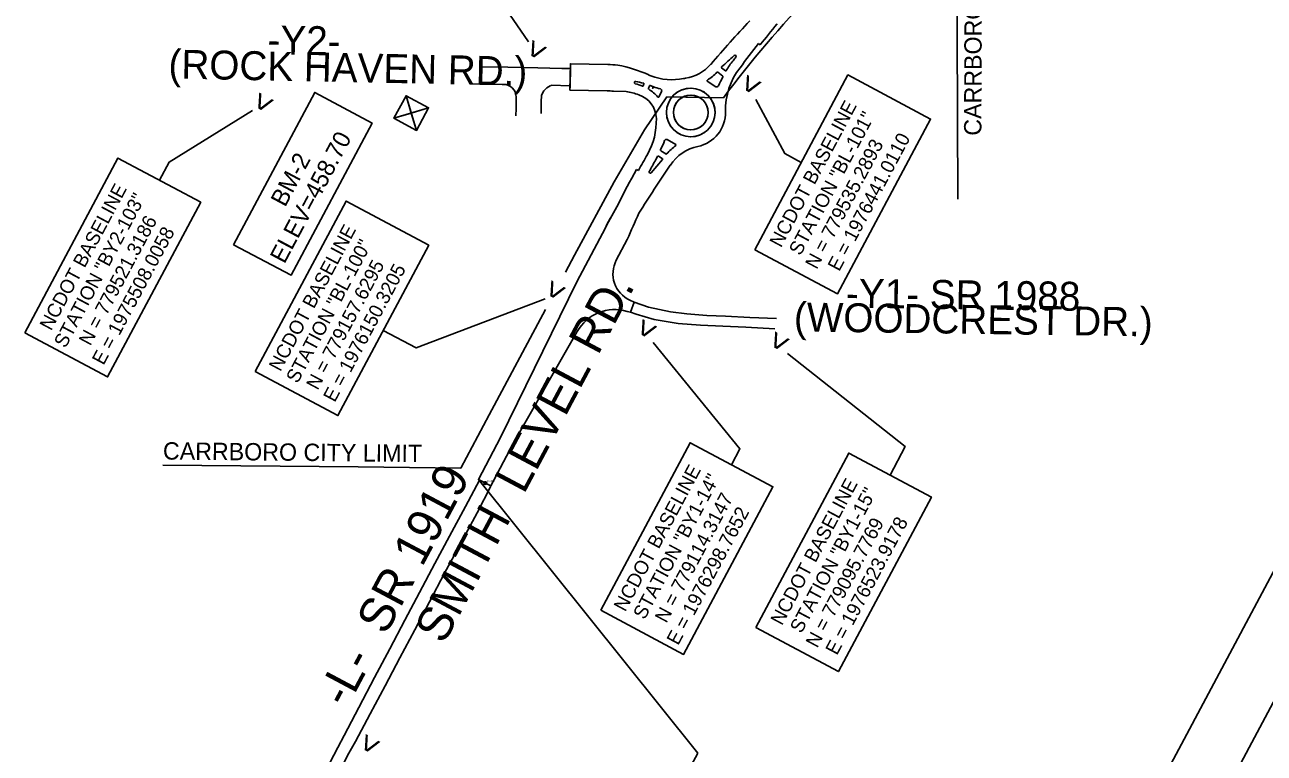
# Model space of a CAD drawing. Extents: x 1970823 to 1988115, y 770601 to 786368.
# Drawn here: x 1975224 to 1977367, y 778367 to 779627 of the extents above; entities that cross this region are included whole.
import ezdxf

# ---------------------------------------------------------------- set-up
doc = ezdxf.new("R2010")
doc.units = 0
for name, color, linetype in [('Cogo Default Point CELL', 7, 'Continuous'), ('COGO Default Point Number', 7, 'Continuous'), ('CTL Sheet Border CELL', 7, 'Continuous'), ('CTL Sheet Text', 7, 'Continuous'), ('CTL Supplemental Horizontal and Vertical Text', 7, 'Continuous'), ('Default', 7, 'Continuous'), ('Old_Level_12', 7, 'Continuous'), ('Old_Level_3', 7, 'Continuous'), ('Old_Level_32', 7, 'Continuous'), ('Old_Level_57', 7, 'Continuous')]:
    doc.layers.add(name, color=color, linetype=linetype)

msp = doc.modelspace()

# ---------------------------------------------------------------- linework, layer by layer
at = {"layer": 'Cogo Default Point CELL'}
for points in [[(1976020.6, 778837.3), (1976020.6, 778834.3)], [(1976017.6, 778834.3), (1976020.6, 778834.3)], [(1976020.6, 778834.3), (1976023.6, 778834.3)], [(1976020.6, 778834.3), (1976020.6, 778831.3)]]:
    msp.add_lwpolyline(points, dxfattribs=at)
msp.add_circle((1976020.6, 778834.3), 2.34, dxfattribs=at)
at = {"layer": 'CTL Sheet Border CELL'}
msp.add_lwpolyline([(1977121.9, 778191.4), (1979828.5, 783270.4), (1979922.1, 783220.5), (1977215.6, 778141.6)], close=True, dxfattribs=at)
at = {"layer": 'CTL Sheet Text'}
for q in [(1976008.8, 778840.5), (1975683.2, 777045.4)]:
    msp.add_line((1976387.7, 778367.4), q, dxfattribs=at)
at = {"layer": 'CTL Supplemental Horizontal and Vertical Text'}
for points in [[(1975932.9, 779797.4), (1975972.3, 779776.4), (1976095.3, 779597.5)], [(1975457.1, 779358.1), (1975473.8, 779389.4), (1975618.1, 779478.3)], [(1976566.9, 779388.8), (1976538.2, 779404), (1976488.3, 779497.8)], [(1975844.3, 779098.3), (1975901.2, 779067.9), (1976123.8, 779152.8)], [(1976446.2, 778865.8), (1976460.7, 778893.2), (1976310.6, 779077.3)], [(1976720.4, 778848.1), (1976746.5, 778897.3), (1976542.8, 779058.3)]]:
    msp.add_lwpolyline(points, dxfattribs=at)
at = {"layer": 'Default'}
for p, q in [((1976492.7, 779594.4), (1976495.8, 779591.9)), ((1976167.8, 779559.3), (1976166.8, 779513.8)), ((1976167.8, 779559.3), (1976232.3, 779558)), ((1976293.7, 779521.2), (1976294.9, 779524.5)), ((1976304.5, 779521.3), (1976302.5, 779516.6)), ((1976404.4, 779529.4), (1976419.2, 779519.7)), ((1976166.8, 779513.8), (1976231.4, 779512.5)), ((1976242.1, 779512.1), (1976263.9, 779511.6)), ((1976320.4, 779501.8), (1976325.2, 779511.5)), ((1976334.9, 779428.2), (1976349.8, 779419.5)), ((1976307.2, 779370.9), (1976326.7, 779394)), ((1976319.9, 779399.7), (1976326.4, 779395.5)), ((1976281.8, 779376.5), (1976285.3, 779374.5)), ((1976178.7, 779182.3), (1976228.2, 779275.9)), ((1976247, 779219.5), (1976266, 779255.5)), ((1976047.1, 778913), (1976178.7, 779182.3)), ((1976278.1, 779147.2), (1976270.5, 779150.7)), ((1976278.1, 779147.2), (1976271.6, 779129.6)), ((1976271.6, 779129.6), (1976266, 779131.2)), ((1976068.3, 778901.8), (1976179.3, 779096.5)), ((1976008.8, 778840.5), (1976047.1, 778913)), ((1976030, 778829.3), (1976068.3, 778901.8)), ((1976008.8, 778840.5), (1976030, 778829.3))]:
    msp.add_line(p, q, dxfattribs=at)
for points in [[(1976492.7, 779594.4), (1976495.8, 779591.9)], [(1976232.3, 779558), (1976167.8, 779559.3), (1976167.6, 779550.9), (1976167, 779520.9), (1976166.8, 779513.8), (1976231.4, 779512.5)], [(1976431.1, 779537.9), (1976422.3, 779544.7)], [(1976422.3, 779544.7), (1976431.1, 779537.9)], [(1976429, 779552.2), (1976435.6, 779547.1)], [(1976435.6, 779547.1), (1976429, 779552.2)], [(1976293.7, 779521.2), (1976294.9, 779524.5)], [(1976294.9, 779524.5), (1976293.7, 779521.2)], [(1976304.5, 779521.3), (1976302.5, 779516.6)], [(1976302.5, 779516.6), (1976304.5, 779521.3)], [(1976404.4, 779529.4), (1976419.2, 779519.7)], [(1976419.2, 779519.7), (1976404.4, 779529.4)], [(1976242.1, 779512.1), (1976263.9, 779511.6)], [(1976311.1, 779519.6), (1976309.8, 779516.7), (1976311.1, 779519.6)], [(1976320.4, 779501.8), (1976325.2, 779511.5)], [(1976325.2, 779511.5), (1976320.4, 779501.8)], [(1976349.8, 779419.5), (1976334.9, 779428.2)], [(1976334.9, 779428.2), (1976349.8, 779419.5)], [(1976307.2, 779370.9), (1976326.7, 779394)], [(1976326.7, 779394), (1976307.2, 779370.9)], [(1976326.4, 779395.5), (1976319.9, 779399.7)], [(1976319.9, 779399.7), (1976326.4, 779395.5)], [(1976323.9, 779409), (1976332.8, 779403.3)], [(1976332.8, 779403.3), (1976323.9, 779409)], [(1976285.3, 779374.5), (1976281.8, 779376.5)], [(1976250.7, 779317.3), (1976250.6, 779317.2)], [(1976228.2, 779275.9), (1976178.7, 779182.3), (1976047.1, 778913), (1976008.8, 778840.5), (1976010.8, 778839.5), (1976030, 778829.3), (1976068.3, 778901.8), (1976179.4, 779096.2)], [(1976247, 779219.5), (1976266, 779255.5)], [(1976266, 779131.2), (1976271.6, 779129.6), (1976278.1, 779147.2), (1976270.5, 779150.7)]]:
    msp.add_lwpolyline(points, dxfattribs=at)
for points in [[(1976486.3, 779237.6), (1976647.4, 779539.9), (1976790.4, 779463.7), (1976629.3, 779161.4)], [(1975585.4, 779246.4), (1975725.7, 779509.7), (1975824.9, 779456.8), (1975684.7, 779193.5)], [(1975224.5, 779093.9), (1975385.6, 779396.2), (1975528.6, 779320), (1975367.5, 779017.7)], [(1975622.8, 779027.1), (1975779.8, 779321.8), (1975922.8, 779245.6), (1975765.7, 778950.9)], [(1976220.3, 778614.3), (1976374.7, 778903.9), (1976517.7, 778827.8), (1976363.3, 778538.1)], [(1976488.1, 778584.6), (1976648.9, 778886.2), (1976791.8, 778810), (1976631.1, 778508.4)]]:
    msp.add_lwpolyline(points, close=True, dxfattribs=at)
for radius in [42, 30]:
    msp.add_circle((1976375.8, 779475.1), radius, dxfattribs=at)
for centre, radius, start, end in [((1977876.3, 778316.7), 1921, 136.7176, 139.7332), ((1977876.3, 778316.7), 1921, 136.7176, 139.7332), ((1977976, 778436), 1878, 140.5977, 142.0125), ((1977976, 778436), 1878, 140.6002, 142.0125), ((1977976.4, 778436.4), 1882, 142.0289, 143.6297), ((1977976.4, 778436.4), 1882, 142.0289, 143.6297), ((1977729.6, 778130.3), 1928.2, 131.5446, 132.4191), ((1977729.6, 778130.3), 1928.2, 131.5446, 132.4191), ((1977729.6, 778130.3), 1928.2, 131.5446, 132.4191), ((1976555.7, 779478.9), 137, 141.2395, 150.018), ((1976555.7, 779478.9), 137, 141.2395, 150.018), ((1976555.7, 779478.9), 137, 141.2395, 150.018), ((1977926.9, 778377.9), 1895.5, 141.0068, 141.2395), ((1977926.9, 778377.9), 1895.5, 141.0068, 141.2395), ((1977926.9, 778377.9), 1895.5, 141.0068, 141.2395), ((1976452.2, 779571.9), 2, 321.0068, 131.5446), ((1976452.2, 779571.9), 2, 321.0068, 131.5446), ((1976452.2, 779571.9), 2, 321.0068, 131.5446), ((1976227.7, 779333.2), 224.8, 84.44, 88.8319), ((1976227.7, 779333.2), 224.8, 84.44, 88.8319), ((1976208.6, 779335), 225.7, 65.2309, 79.5481), ((1976208.6, 779335), 225.7, 65.2309, 79.5481), ((1976354.8, 779608.5), 75, 278.9494, 318.0674), ((1976354.8, 779608.5), 75, 278.9494, 318.0674), ((1976354.8, 779608.5), 92, 302.6674, 316.0364), ((1976354.8, 779608.5), 92, 302.6674, 316.0364), ((1976354.8, 779608.5), 92, 302.6674, 316.0364), ((1976421.7, 779543.9), 1, 52.2081, 136.0364), ((1976421.7, 779543.9), 1, 52.2081, 136.0364), ((1976421.7, 779543.9), 1, 52.2081, 136.0364), ((1976429.6, 779553), 1, 132.4191, 231.9065), ((1976429.6, 779553), 1, 132.4191, 231.9065), ((1976429.6, 779553), 1, 132.4191, 231.9065), ((1976436.2, 779547.8), 1, 231.9065, 330.018), ((1976436.2, 779547.8), 1, 231.9065, 330.018), ((1976436.2, 779547.8), 1, 231.9065, 330.018), ((1976555.7, 779478.9), 120, 142.1787, 181.1936), ((1976555.7, 779478.9), 120, 142.1787, 181.1936), ((1976280.2, 779526.8), 2, 79.4395, 253.1009), ((1976280.2, 779526.8), 2, 79.4395, 253.1009), ((1976280.2, 779526.8), 2, 79.4395, 253.1009), ((1976221.4, 779333.1), 200.4, 69.2746, 73.1009), ((1976221.4, 779333.1), 200.4, 69.2746, 73.1009), ((1976221.4, 779333.1), 200.4, 69.2746, 73.1009), ((1976243.4, 779329.6), 202.6, 75.4924, 79.4395), ((1976243.4, 779329.6), 202.6, 75.4924, 79.4395), ((1976243.4, 779329.6), 202.6, 75.4924, 79.4395), ((1976292.8, 779521.5), 1, 241.0006, 340.6492), ((1976292.8, 779521.5), 1, 241.0006, 340.6492), ((1976292.8, 779521.5), 1, 241.0006, 340.6492), ((1976293.9, 779524.8), 1, 340.6492, 75.4924), ((1976293.9, 779524.8), 1, 340.6492, 75.4924), ((1976293.9, 779524.8), 1, 340.6492, 75.4924), ((1976227.7, 779333.2), 220, 68.8787, 69.9595), ((1976227.7, 779333.2), 220, 68.8787, 69.9595), ((1976305.4, 779520.9), 1, 66.3367, 157.7992), ((1976305.4, 779520.9), 1, 66.3367, 157.7992), ((1976305.4, 779520.9), 1, 66.3367, 157.7992), ((1976352.7, 779628.9), 116.9, 246.3367, 255.4103), ((1976352.7, 779628.9), 116.9, 246.3367, 249.1392), ((1976352.7, 779628.9), 116.9, 246.3367, 249.1392), ((1976343, 779631.8), 100, 248.8787, 281.7975), ((1976343, 779631.8), 100, 248.8787, 281.7975), ((1976375.8, 779475.1), 60, 98.9494, 101.7975), ((1976375.8, 779475.1), 60, 98.9494, 101.7975), ((1976405, 779530.2), 1, 122.6674, 236.722), ((1976405, 779530.2), 1, 122.6674, 236.722), ((1976405, 779530.2), 1, 122.6674, 236.722), ((1976420.8, 779522.2), 3, 236.722, 337.1435), ((1976420.8, 779522.2), 3, 236.722, 337.1435), ((1976420.8, 779522.2), 3, 236.722, 337.1435), ((1976548.8, 779468.2), 135.8, 149.792, 157.1435), ((1976548.8, 779468.2), 135.8, 149.792, 157.1435), ((1976548.8, 779468.2), 135.8, 149.792, 157.1435), ((1976430.5, 779537.1), 1, 329.792, 52.2081), ((1976430.5, 779537.1), 1, 329.792, 52.2081), ((1976430.5, 779537.1), 1, 329.792, 52.2081), ((1976227.7, 779331.4), 181.1, 87.2818, 88.8319), ((1976227.7, 779331.4), 181.1, 87.2818, 88.8319), ((1976231.4, 779329), 183.3, 86.6752, 88.4912), ((1976231.4, 779329), 183.3, 86.6752, 88.4912), ((1976227.7, 779333.2), 182, 71.3914, 78.5258), ((1976227.7, 779333.2), 182, 71.3914, 78.5258), ((1976271.4, 779463.2), 44.9, 1.7826, 71.2258), ((1976271.4, 779463.2), 44.9, 1.7826, 71.2258), ((1976303.5, 779516.2), 1, 157.7992, 238.9047), ((1976303.5, 779516.2), 1, 157.7992, 238.9047), ((1976303.5, 779516.2), 1, 157.7992, 238.9047), ((1976271.5, 779463.1), 61, 39.1963, 58.9047), ((1976271.5, 779463.1), 61, 39.1963, 58.9047), ((1976271.5, 779463.1), 61, 39.1963, 58.9047), ((1976352.7, 779628.9), 116.9, 249.1392, 255.4103), ((1976352.7, 779628.9), 116.9, 249.1392, 255.4103), ((1976319.5, 779502.3), 1, 219.1963, 333.6015), ((1976319.5, 779502.3), 1, 219.1963, 333.6015), ((1976319.5, 779502.3), 1, 219.1963, 333.6015), ((1976322.5, 779512.8), 3, 333.6015, 75.4103), ((1976322.5, 779512.8), 3, 333.6015, 75.4103), ((1976322.5, 779512.8), 3, 333.6015, 75.4103), ((1976375.8, 779475.1), 42, 55.3305, 235.3305), ((1976375.8, 779475.1), 42, 55.3305, 235.3305), ((1976375.8, 779475.1), 30, 55.1797, 235.1797), ((1976375.8, 779475.1), 42, 235.3305, 55.3305), ((1976375.8, 779475.1), 42, 235.3305, 55.3305), ((1976375.8, 779475.1), 30, 235.1797, 55.1797), ((1976196.2, 779461.3), 120.1, 330.7248, 1.5795), ((1976196.2, 779461.3), 120.1, 330.7248, 1.5795), ((1976375.8, 779475.1), 60, 281.7976, 1.1936), ((1976375.8, 779475.1), 60, 281.7976, 1.1936), ((1976202, 779472.3), 136.4, 332.9755, 340.4471), ((1976202, 779472.3), 136.4, 332.9755, 340.4471), ((1976202, 779472.3), 136.4, 332.9755, 340.4471), ((1976333.4, 779425.6), 3, 59.8207, 160.4471), ((1976333.4, 779425.6), 3, 59.8207, 160.4471), ((1976333.4, 779425.6), 3, 59.8207, 160.4471), ((1976403.4, 779343), 92, 125.5201, 138.8781), ((1976403.4, 779343), 92, 125.5201, 138.8781), ((1976403.4, 779343), 92, 125.5201, 138.8781), ((1976403.4, 779343), 75, 101.7976, 147.0005), ((1976403.4, 779343), 75, 101.7976, 147.0005), ((1976349.3, 779418.7), 1, 305.5201, 59.8207), ((1976349.3, 779418.7), 1, 305.5201, 59.8207), ((1976349.3, 779418.7), 1, 305.5201, 59.8207), ((1977970.7, 778451.4), 1921.7, 150.3325, 151.2896), ((1977970.7, 778451.4), 1921.7, 150.3325, 151.2896), ((1977680.5, 778615.6), 1571.2, 150.3557, 151.1771), ((1977680.5, 778615.6), 1571.2, 150.3557, 151.1771), ((1977680.5, 778615.6), 1571.2, 150.3557, 151.1771), ((1976196.2, 779461.3), 137.1, 330.0114, 333.1049), ((1976196.2, 779461.3), 137.1, 330.0114, 333.1049), ((1976196.2, 779461.3), 137.1, 330.0114, 333.1049), ((1976319.4, 779398.8), 1, 57.5529, 153.1049), ((1976319.4, 779398.8), 1, 57.5529, 153.1049), ((1976319.4, 779398.8), 1, 57.5529, 153.1049), ((1976324.4, 779409.9), 1, 152.9755, 237.2513), ((1976324.4, 779409.9), 1, 152.9755, 237.2513), ((1976324.4, 779409.9), 1, 152.9755, 237.2513), ((1976325.9, 779394.7), 1, 319.9706, 57.5529), ((1976325.9, 779394.7), 1, 319.9706, 57.5529), ((1976325.9, 779394.7), 1, 319.9706, 57.5529), ((1976333.3, 779404.1), 1, 237.2513, 318.8781), ((1976333.3, 779404.1), 1, 237.2513, 318.8781), ((1976333.3, 779404.1), 1, 237.2513, 318.8781), ((1977970.7, 778451.4), 1925.7, 151.2896, 153.2826), ((1977970.7, 778451.4), 1925.7, 151.2896, 153.2799), ((1977887.9, 778312.7), 1882, 145.31, 148.3291), ((1977887.9, 778312.7), 1882, 145.31, 148.3291), ((1976305.7, 779372.1), 2, 151.1771, 319.9706), ((1976305.7, 779372.1), 2, 151.1771, 319.9706), ((1976305.7, 779372.1), 2, 151.1771, 319.9706), ((1977926.9, 778377.9), 1921.5, 150.7331, 152.1381), ((1977926.9, 778377.9), 1921.5, 150.7357, 152.1381), ((1977970.7, 778451.4), 1925.7, 153.2799, 153.2826), ((1977926.9, 778377.9), 1921.5, 150.7331, 150.7357), ((1977999.7, 778511.4), 1886.6, 155.2633, 156.7713), ((1977999.7, 778511.4), 1886.6, 155.2633, 156.7713), ((1976291.2, 779196.2), 50, 152.1381, 245.532), ((1976291.2, 779196.2), 50, 152.1381, 245.532), ((1976244.7, 779059.3), 75, 73.5208, 150.5633), ((1976244.7, 779059.3), 75, 73.5208, 150.5633)]:
    msp.add_arc(centre, radius, start, end, dxfattribs=at)
at = {"layer": 'Old_Level_12'}
for p, q in [((1976295.6, 779444.8), (1976334.6, 779502.4)), ((1976334.6, 779502.4), (1976432.1, 779500.4)), ((1976243.1, 779355.2), (1976295.6, 779444.8)), ((1976175, 779228.2), (1976243.1, 779355.2)), ((1976159.4, 779199), (1976175, 779228.2)), ((1976027.4, 778952), (1976124.9, 779134.4))]:
    msp.add_line(p, q, dxfattribs=at)
for points in [[(1976837.1, 779939), (1976836.2, 779613), (1976837.5, 779325.2)], [(1975463.2, 778865.5), (1975800.9, 778862.2), (1975978.1, 778859.8), (1976027.4, 778952)]]:
    msp.add_lwpolyline(points, dxfattribs=at)
msp.add_arc((1977861.3, 778440.4), 1779.3, 135.7394, 143.4363, dxfattribs=at)
at = {"layer": 'Old_Level_3'}
msp.add_line((1976011.7, 779524.2), (1976025.6, 779524), dxfattribs=at)
for points in [[(1976167.6, 779550.9), (1976152.9, 779551.2), (1976111.5, 779552.1), (1976059.4, 779553.2), (1976012.3, 779554.1)], [(1975999.1, 779524.5), (1976010.6, 779524.3)], [(1976056.8, 779523.4), (1976049.9, 779523.4), (1976028.4, 779523.9)], [(1976056.6, 779523.4), (1976060.9, 779521.9), (1976064.1, 779520.2), (1976066.9, 779517.9), (1976070.7, 779513.6), (1976072, 779510.8), (1976073.5, 779506.5), (1976074, 779500.8), (1976073.8, 779482), (1976073.5, 779469.2)], [(1976117.7, 779504.6), (1976119.3, 779508.6), (1976122, 779512.7), (1976126.7, 779517.5), (1976132.8, 779521.3), (1976133.9, 779521.6)], [(1976167, 779520.9), (1976134.4, 779522.1)], [(1976117, 779473.3), (1976117.3, 779484), (1976117.4, 779493.6), (1976117.7, 779504.6)], [(1976278.1, 779147.2), (1976302.7, 779138.6), (1976340.9, 779130.1), (1976368.7, 779127), (1976403.8, 779124.3), (1976435.7, 779122.6), (1976477.7, 779120.7), (1976524, 779119.1)], [(1976271.6, 779129.7), (1976281.6, 779126.6), (1976312.5, 779117), (1976354, 779110), (1976392.8, 779107.3), (1976431.2, 779105.6), (1976470.7, 779104), (1976521, 779101.2)], [(1975986.4, 778793.7), (1976010.8, 778839.4)], [(1976006.3, 778783), (1976030.4, 778829.1)], [(1975776.4, 778398), (1975801.7, 778446.2), (1975829.1, 778498.1), (1975855.3, 778547.7), (1975881.3, 778597), (1975906.9, 778645.3), (1975933.6, 778695.5), (1975958.6, 778742.5), (1975986.4, 778793.7)], [(1975796.4, 778387.4), (1975821.7, 778435.2), (1975847.5, 778483.8), (1975873, 778532.1), (1975898.6, 778580.8), (1975924, 778629.1), (1975950.1, 778678.4), (1975967, 778708.9), (1975969.6, 778711.2), (1975980.8, 778730.9), (1975982.6, 778737.8), (1976006.3, 778783)], [(1975572.1, 777985.9), (1975581.2, 778008.3), (1975595.3, 778040.6), (1975616.5, 778084.7), (1975640.5, 778133), (1975672.6, 778197.2), (1975700.2, 778250.6), (1975731.3, 778310.8), (1975765.5, 778377.1), (1975776.4, 778398)], [(1975592.2, 777977.8), (1975601, 778000), (1975614.9, 778031.5), (1975635.9, 778075), (1975659.8, 778123.4), (1975692, 778187.7), (1975719.2, 778240.6), (1975750.5, 778300.9), (1975784.7, 778367), (1975796.4, 778387.4)]]:
    msp.add_lwpolyline(points, dxfattribs=at)
at = {"layer": 'Old_Level_57'}
for p, q in [((1975901.7, 779444.2), (1975883.5, 779504)), ((1975922.5, 779483.2), (1975862.7, 779465))]:
    msp.add_line(p, q, dxfattribs=at)
msp.add_lwpolyline([(1975883.5, 779504), (1975862.7, 779465), (1975901.7, 779444.2), (1975922.5, 779483.2)], close=True, dxfattribs=at)
for points in [[(1975892.6, 779474.1), (1975883.5, 779504), (1975862.7, 779465), (1975892.6, 779474.1)], [(1975892.6, 779474.1), (1975901.7, 779444.2), (1975922.5, 779483.2), (1975892.6, 779474.1)]]:
    msp.add_lwpolyline(points, dxfattribs=at)

# ---------------------------------------------------------------- texts
at = {"layer": 'COGO Default Point Number'}
msp.add_text('BEGIN01', height=2.5, dxfattribs=at).set_placement((1976023.1, 778836.8))
at = {"layer": 'CTL Sheet Text'}
for s, height, rotation, p in [('-Y2- ', 50, 358.8319, (1975643.6, 779576)), ('(ROCK HAVEN RD.)', 50, 358.8319, (1975472.5, 779534)), ('-Y1- SR 1988', 50, 359.1816, (1976643.8, 779137.8)), ('SMITH  LEVEL RD.', 60, 61.9471, (1975948.8, 778553.8)), ('(WOODCREST DR.)', 50, 359.1816, (1976553.8, 779096.7)), ('-L-  SR 1919', 60, 61.9471, (1975781.3, 778443.7))]:
    msp.add_text(s, height=height, rotation=rotation, dxfattribs=at).set_placement(p)
at = {"layer": 'CTL Supplemental Horizontal and Vertical Text'}
for s, height, p in [('NCDOT BASELINE', 24, (1976531.8, 779240.1)), ('STATION "BL-101"', 24, (1976565.3, 779226.2)), ('ELEV=458.70', 30, (1975673.3, 779212)), ('E = 1976441.0110', 24, (1976632.3, 779198.9)), ('N = 779535.2893', 24, (1976593.4, 779202.5)), ('BM-2', 30, (1975674.5, 779310.1)), ('NCDOT BASELINE', 24, (1975270, 779096.4)), ('STATION "BY2-103"', 24, (1975294.8, 779066.3)), ('N = 779521.3186', 24, (1975337.7, 779070.3)), ('E = 1975508.0058', 24, (1975360.6, 779036.8)), ('NCDOT BASELINE', 24, (1975666.3, 779025.8)), ('STATION "BL-100"', 24, (1975696, 779005.1)), ('N = 779157.6295', 24, (1975730.7, 778993.7)), ('E = 1976150.3205', 24, (1975760.3, 778972.6)), ('NCDOT BASELINE', 24, (1976262.5, 778610.4)), ('STATION "BY1-14"', 24, (1976296, 778596.8)), ('NCDOT BASELINE', 24, (1976533.5, 778586.7)), ('N = 779114.3147', 24, (1976333.6, 778590.8)), ('STATION "BY1-15"', 24, (1976567, 778573)), ('E = 1976298.7652', 24, (1976353.9, 778552.4)), ('N = 779095.7769', 24, (1976594.3, 778547.8)), ('E = 1976523.9178', 24, (1976628.4, 778535.2))]:
    msp.add_text(s, height=height, rotation=61.9471, dxfattribs=at).set_placement(p)
at = {"layer": 'Old_Level_32'}
for rotation, p in [(89.85, (1976878.2, 779434.9)), (359.4291, (1975463.2, 778875))]:
    msp.add_text('CARRBORO CITY LIMIT', height=30, rotation=rotation, dxfattribs=at).set_placement(p)
at = {"layer": 'Old_Level_57'}
for p in [(1976099.4, 779605), (1976470.4, 779544.9), (1975627.2, 779514.1), (1976132.1, 779189.4), (1976289.9, 779122.5), (1976519.1, 779100.7), (1975811.3, 778404.6)]:
    msp.add_text('>', height=39.1, rotation=241.9613, dxfattribs=at).set_placement(p)

doc.saveas('drawing.dxf')
